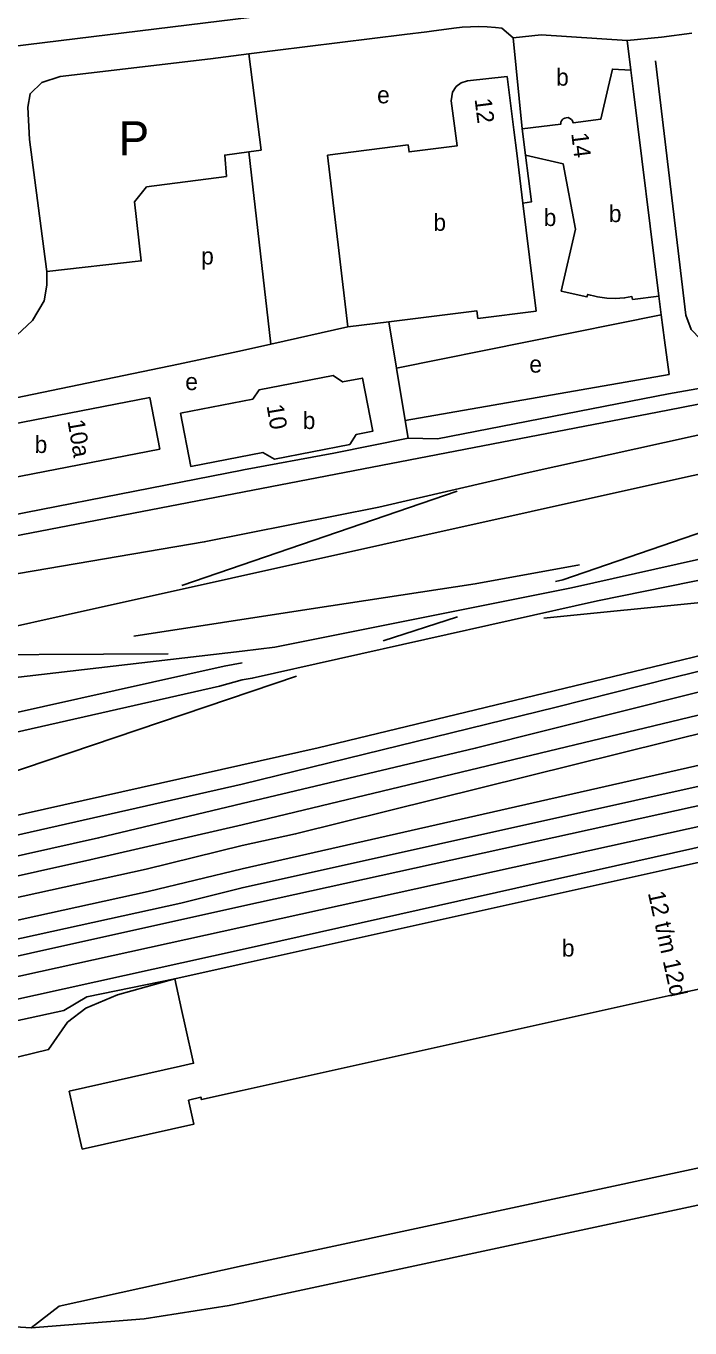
# Model space of a CAD drawing. Extents: x 161494 to 163033, y 383688 to 384862.
# Drawn here: x 161849.3 to 162005.1, y 383712.3 to 384018.2 of the extents above; entities that cross this region are included whole.
import ezdxf

# ---------------------------------------------------------------- set-up
doc = ezdxf.new("R2010")
doc.units = 0
for name, color, linetype in [('BLT_Basislijn', 7, 'Continuous'), ('BLT_Bebouwing', 7, 'Continuous'), ('BLT_Centroide', 7, 'Continuous'), ('BLT_Huisnummer', 7, 'Continuous'), ('BLT_Huisnummer_reeks', 7, 'Continuous'), ('BLT_Onderverdeling_panden', 7, 'Continuous'), ('BLT_Spoorlijn', 7, 'Continuous'), ('BLT_Straatnaam_hoofdweg', 7, 'Continuous'), ('BLT_Tekst_parkeren', 7, 'Continuous')]:
    doc.layers.add(name, color=color, linetype=linetype)

msp = doc.modelspace()

# ---------------------------------------------------------------- linework, layer by layer
at = {"layer": 'BLT_Basislijn'}
for p, q in [((161938.14, 384016.18), (161943.33, 384016.83)), ((161943.33, 384016.83), (161944.44, 384016.98)), ((161944.44, 384016.98), (161949.74, 384017.67)), ((161960.98, 384017.69), (161963.65, 384015.42)), ((161907.77, 384012.39), (161938.14, 384016.18)), ((161990.44, 384014.8), (161998.45, 384015.55)), ((162005.59, 384016.47), (161998.45, 384015.55)), ((161892.55, 384010.49), (161901.55, 384011.61)), ((161901.55, 384011.61), (161907.77, 384012.39)), ((161901.55, 383988.64), (161906.76, 383943.41)), ((161924.79, 383947.48), (161906.76, 383943.41)), ((161906.76, 383943.41), (161900.11, 383941.91)), ((161900.11, 383941.91), (161885.02, 383938.77)), ((161885.02, 383938.77), (161827.95, 383926.88)), ((161936.24, 383937.81), (161938.26, 383925.54)), ((162000.26, 383936.32), (161938.26, 383925.54)), ((161938.26, 383925.54), (161938.95, 383921.37)), ((161857.05, 383717.49), (161850.45, 383712.34))]:
    msp.add_line(p, q, dxfattribs=at)
for points in [[(162956.78, 384021.72), (162940.81, 384022.86), (162844.13, 384032.25), (162776, 384038.39), (162705.31, 384043.59), (162655, 384044.9), (162627.45, 384044.8), (162579.26, 384042.49), (162510.26, 384034.87), (162452.51, 384024.7), (162377.46, 384008.85), (162301.58, 383991.65), (162233.15, 383976.81), (162161.35, 383961.08), (162082.65, 383946.35), (162000.1, 383931.74), (161945.86, 383921.22), (161938.95, 383921.37)], [(161959.65, 384027.27), (161916.99, 384022.03), (161846.02, 384013.32)], [(161949.74, 384017.67), (161951.68, 384017.87), (161953.63, 384017.98), (161955.57, 384018.02), (161957.52, 384017.97), (161959.47, 384017.85), (161960.98, 384017.69)], [(161901.55, 383988.64), (161904.45, 383989.04), (161901.55, 384011.61)], [(161854.11, 383960.54), (161854.1, 383961.03), (161850.06, 383991.47), (161849.69, 383999.11), (161850.2, 384002.26), (161852.95, 384004.89), (161857.27, 384006.32), (161892.55, 384010.49)], [(161997.08, 384010.02), (162004.14, 383950.22), (162005.39, 383946.88), (162007.62, 383944.64), (162015.93, 383944.83), (162042.51, 383948.79)], [(161896.36, 383982.8), (161895.9, 383987.86), (161901.55, 383988.64)], [(161854.11, 383960.54), (161876.33, 383963), (161874.74, 383976.83), (161877.56, 383980.39), (161896.36, 383982.8)], [(161827.95, 383926.88), (161834.08, 383932.99), (161836.84, 383935.47), (161844.57, 383943.19), (161850.77, 383949.03), (161853.48, 383953.65), (161854.18, 383957.29), (161854.11, 383960.54)], [(161999.18, 383944.41), (161998.35, 383950.36)], [(161999.18, 383944.41), (162000.26, 383936.32)], [(161938.95, 383921.37), (161921.54, 383917.84), (161900.32, 383913.91)], [(161823.92, 383898.93), (161900, 383913.85), (161900.32, 383913.91)], [(161857.05, 383717.49), (161900, 383726.97), (162020.37, 383752.79), (162087.25, 383768.84), (162248.7, 383805.52), (162255.21, 383807.22), (162293.41, 383819.32), (162294.37, 383819.23), (162295.04, 383818.42), (162296.07, 383817.77)], [(162298.39, 383814.86), (162298.2, 383810.83), (162297.43, 383809.38), (162296.37, 383808.09), (162294.68, 383807.19), (162245.95, 383797.11), (162194.64, 383781.44), (161900, 383718.26), (161896.94, 383717.62), (161877.03, 383714.47), (161850.45, 383712.34)], [(161884.2, 383794.32), (161863.54, 383790.11), (161858.12, 383786.9), (161822.86, 383779.21), (161824.12, 383768.62)], [(161840.05, 383774.26), (161854.57, 383777.72), (161858.96, 383784.17), (161863.29, 383787.44), (161870.76, 383790.62), (161884.2, 383794.32)], [(161850.45, 383712.34), (161842.81, 383712.87), (161826.62, 383713.33)]]:
    msp.add_lwpolyline(points, dxfattribs=at)
at = {"layer": 'BLT_Bebouwing'}
for p, q in [((161963.65, 384015.42), (161965.77, 383993.98)), ((161990.44, 384014.8), (161991.26, 384007.83)), ((161991.26, 384007.83), (161991.84, 384003.44)), ((161962.25, 384006.34), (161963.79, 383993.74)), ((161997.81, 383954.73), (161991.84, 384003.44)), ((161963.79, 383993.74), (161964.46, 383988.27)), ((161965.77, 383993.98), (161966.54, 383987.8)), ((161939, 383990.24), (161920.02, 383987.86)), ((161920.02, 383987.86), (161922.74, 383965.46)), ((161964.46, 383988.27), (161965.9, 383976.57)), ((161997.81, 383954.73), (161998.35, 383950.36)), ((161936.24, 383937.81), (161998.35, 383950.36)), ((161884.2, 383794.32), (161884.59, 383792.55)), ((161884.59, 383792.55), (161885.8, 383787.14)), ((161885.8, 383787.14), (161886.66, 383783.28)), ((161885.49, 383773.82), (161859.41, 383768)), ((161859.41, 383768), (161861.77, 383757.43))]:
    msp.add_line(p, q, dxfattribs=at)
for points in [[(161990.44, 384014.8), (161970.21, 384016.08), (161963.65, 384015.42)], [(161939, 383990.24), (161939.2, 383988.6), (161950.48, 383989.99), (161949.1, 384000.56), (161949.37, 384002.59), (161950.28, 384003.92), (161951.46, 384004.83), (161952.92, 384005.25), (161962.25, 384006.34)], [(161966.54, 383987.8), (161967.92, 383976.83), (161965.9, 383976.57)], [(161922.74, 383965.46), (161924.79, 383947.48)], [(161924.79, 383947.48), (161934.45, 383948.68)], [(161934.45, 383948.68), (161936.24, 383937.81)], [(161885.53, 383927.22), (161902.48, 383930.5), (161903.97, 383932.7), (161921.4, 383936.07)], [(161921.4, 383936.07), (161923.58, 383934.58), (161928.25, 383935.48), (161930.67, 383922.96), (161926.81, 383922.22), (161925.32, 383919.88)], [(161840.34, 383923.54), (161878.3, 383930.89), (161880.65, 383918.77), (161842.69, 383911.42), (161841.66, 383916.72)], [(161925.32, 383919.88), (161907.59, 383916.44), (161904.82, 383917.98), (161887.95, 383914.72), (161885.53, 383927.22)], [(162000, 383790.34), (162134.33, 383819.8), (162130.48, 383837.21), (162140.9, 383839.53), (162139.81, 383844.85)], [(162139.81, 383844.85), (162089.38, 383833.76), (162088.04, 383839.79), (162000, 383820.13)], [(162000, 383820.13), (161900, 383797.84), (161884.2, 383794.32)], [(161887.37, 383765.86), (161890.33, 383766.52), (161890.45, 383765.98), (161900, 383768.11), (162000, 383790.34)], [(161886.66, 383783.28), (161888.61, 383774.51), (161885.49, 383773.82)], [(161861.77, 383757.43), (161862.46, 383754.35), (161888.64, 383760.19), (161887.37, 383765.86)]]:
    msp.add_lwpolyline(points, dxfattribs=at)
at = {"layer": 'BLT_Onderverdeling_panden'}
for p, q in [((161965.9, 383976.57), (161969.01, 383951.22)), ((161969.01, 383951.22), (161955.36, 383949.45))]:
    msp.add_line(p, q, dxfattribs=at)
for points in [[(161985.95, 384003.76), (161986.93, 384008.04), (161991.26, 384007.83)], [(161965.77, 383993.98), (161974.8, 383995.1), (161974.85, 383995.58), (161974.98, 383995.9), (161975.14, 383996.1), (161975.39, 383996.35), (161975.75, 383996.55), (161976.1, 383996.63), (161976.52, 383996.64), (161976.93, 383996.47), (161977.3, 383996.21), (161977.56, 383995.9), (161977.7, 383995.46), (161984.21, 383996.26), (161985.95, 384003.76)], [(161966.54, 383987.8), (161975.41, 383985.77), (161978.26, 383970.44), (161974.9, 383955.92)], [(161974.9, 383955.92), (161980.96, 383954.52), (161981.13, 383955.11), (161981.78, 383954.91), (161982.53, 383954.75), (161983.45, 383954.52), (161984.57, 383954.41), (161985.6, 383954.24), (161987.58, 383954.19), (161989.81, 383954.3), (161991.53, 383954.6), (161991.65, 383953.96)], [(161991.65, 383953.96), (161997.81, 383954.73)], [(161934.45, 383948.68), (161955.12, 383951.24), (161955.36, 383949.45)]]:
    msp.add_lwpolyline(points, dxfattribs=at)
at = {"layer": 'BLT_Spoorlijn'}
msp.add_line((161950.49, 383908.94), (161885.82, 383886.74), dxfattribs=at)
for points in [[(162900.86, 384011.36), (162871.5, 384014.34), (162849.2, 384016.61), (162786.11, 384023.02), (162743.32, 384027.37), (162714.49, 384029.62), (162675.59, 384031.05), (162617.43, 384030.81), (162571.29, 384028.11), (162530.64, 384023.81), (162498.89, 384019.36), (162460.78, 384012.83), (162360.78, 383991.35), (162187.34, 383952.61), (162103.09, 383933.78), (162003.41, 383912.03), (161897.47, 383888.44), (161858.44, 383879.75), (161796.71, 383866.01)], [(162941.48, 383999.68), (162885.08, 384004.73), (162828.99, 384008.31), (162785.99, 384009.38), (162740.84, 384009.38), (162711.24, 384008.27), (162666.85, 384005.72), (162629.14, 384002.14), (162592.38, 383997.29), (162554.12, 383991.4), (162521.58, 383985.67), (162460.79, 383972.63), (162306.5, 383938.7), (162091.55, 383890.56), (161917.85, 383848.6), (161738.59, 383808.47)], [(162905.58, 383999.21), (162868.86, 384001.46), (162849.7, 384002.66), (162790.91, 384004.97), (162738.08, 384005.04), (162706.63, 384003.77), (162665.91, 384000.87), (162614.64, 383996.13), (162600, 383994.1), (162581.38, 383991.52), (162547.62, 383985.93), (162505.3, 383977.83), (162222.56, 383916.14), (162220.88, 383915.5), (162180.02, 383906.4), (162114.68, 383891.49), (162057.27, 383878.89), (162001, 383865.09), (161973.74, 383858.18), (161900, 383840.1), (161740.55, 383804.02)], [(161730.85, 383826.01), (161894.71, 383863.07), (161900, 383864.57), (161902.38, 383864.96), (161983.42, 383883.13), (162016.6, 383889.91), (162039.67, 383893.48), (162116.35, 383903.49), (162138.72, 383907.4), (162232.76, 383928.3), (162232.82, 383928.45), (162238.5, 383929.73), (162238.57, 383929.89), (162495.51, 383986.06), (162549.61, 383996.68)], [(162395.33, 383979.18), (162144.35, 383923.63), (161977.36, 383886.22), (161907.71, 383872.27), (161900, 383871.29), (161780.14, 383857.4), (161723.5, 383844.79)], [(161717.09, 383867.34), (161891.12, 383897), (161932.12, 383905.15), (161966.91, 383913.19), (162031.41, 383927.43), (162056.89, 383932.93), (162099.3, 383942.63)], [(161973.61, 383887.7), (161975.27, 383888.11), (162047.51, 383912.9), (162078.57, 383923.36), (162115.77, 383935.53), (162118.45, 383936.24)], [(162032.72, 383934.33), (161999.97, 383927.9)], [(161999.97, 383927.9), (161846.12, 383898.23), (161846.53, 383898.23)], [(162256.39, 383917.91), (162217.24, 383909.43), (162209.3, 383907.49), (162022.98, 383865.7), (161954.74, 383848.51), (161900, 383835.54), (161866.29, 383827.45), (161742.42, 383799.74)], [(161754.32, 383769.07), (161900, 383801.22), (162098.04, 383845.62), (162164.2, 383860.2), (162165.2, 383860.57), (162396.44, 383911.1), (162403.33, 383912.46)], [(162166.47, 383892.65), (162054.27, 383867.61), (161900, 383830.52), (161864.25, 383822.27), (161744.09, 383795.55)], [(161979.19, 383891.59), (161954.74, 383887.15), (161916.21, 383881.25), (161874.56, 383874.87)], [(162084.52, 383890.44), (161970.83, 383879.04)], [(161933.09, 383873.73), (161950.55, 383879.42)], [(161821.89, 383870.38), (161882.64, 383870.66)], [(161900, 383868.61), (161895.78, 383867.81), (161827.71, 383852.63), (161728.91, 383830.42)], [(162130.47, 383867.03), (161900, 383815.76), (161885.6, 383812.15), (161749.42, 383782.25)], [(162054.25, 383866.57), (162021.59, 383855.48), (161912.53, 383828.39), (161900, 383825.65), (161877.44, 383820.08), (161745.83, 383791.21)], [(161912.76, 383865.42), (161838.19, 383840.24), (161812.17, 383831.86), (161765.38, 383815.26)], [(162061.12, 383856.79), (161900, 383820.16), (161877.93, 383814.9), (161747.79, 383786.3)], [(162091.56, 383853.64), (161899.96, 383811.43), (161751, 383778.31)], [(162050.18, 383839.64), (161899.96, 383806.47), (161752.71, 383774.04)]]:
    msp.add_lwpolyline(points, dxfattribs=at)

# ---------------------------------------------------------------- texts
at = {"layer": 'BLT_Centroide'}
for s, p in [('b', (161973.72, 384004.15)), ('e', (161931.69, 384000)), ('b', (161944.9, 383970.05)), ('b', (161970.8, 383971.18)), ('b', (161986.1, 383972.1)), ('p', (161890.38, 383962.15)), ('e', (161967.43, 383936.75)), ('e', (161886.65, 383932.64)), ('b', (161914.22, 383923.5)), ('b', (161851.28, 383917.87)), ('b', (161975.07, 383799.59))]:
    msp.add_text(s, height=4, dxfattribs=at).set_placement(p)
at = {"layer": 'BLT_Huisnummer'}
for s, rotation, p in [('12', 277.124, (161954.57, 384000.99)), ('14', 277.124, (161977.26, 383992.91)), ('10', 279.6323, (161905.72, 383928.99)), ('10a', 279.6323, (161858.98, 383925.42))]:
    msp.add_text(s, height=4, rotation=rotation, dxfattribs=at).set_placement(p)
at = {"layer": 'BLT_Huisnummer_reeks'}
msp.add_text('12 t/m 12d', height=4, rotation=282.3724, dxfattribs=at).set_placement((161995.24, 383814.54))
at = {"layer": 'BLT_Straatnaam_hoofdweg'}
msp.add_text('PROFESSOR DR DORGELOLAAN', height=8, rotation=6.4466, dxfattribs=at).set_placement((161692.04, 384006.18))
at = {"layer": 'BLT_Tekst_parkeren'}
msp.add_text('P', height=8, dxfattribs=at).set_placement((161871.03, 383987.79))

doc.saveas('drawing.dxf')
